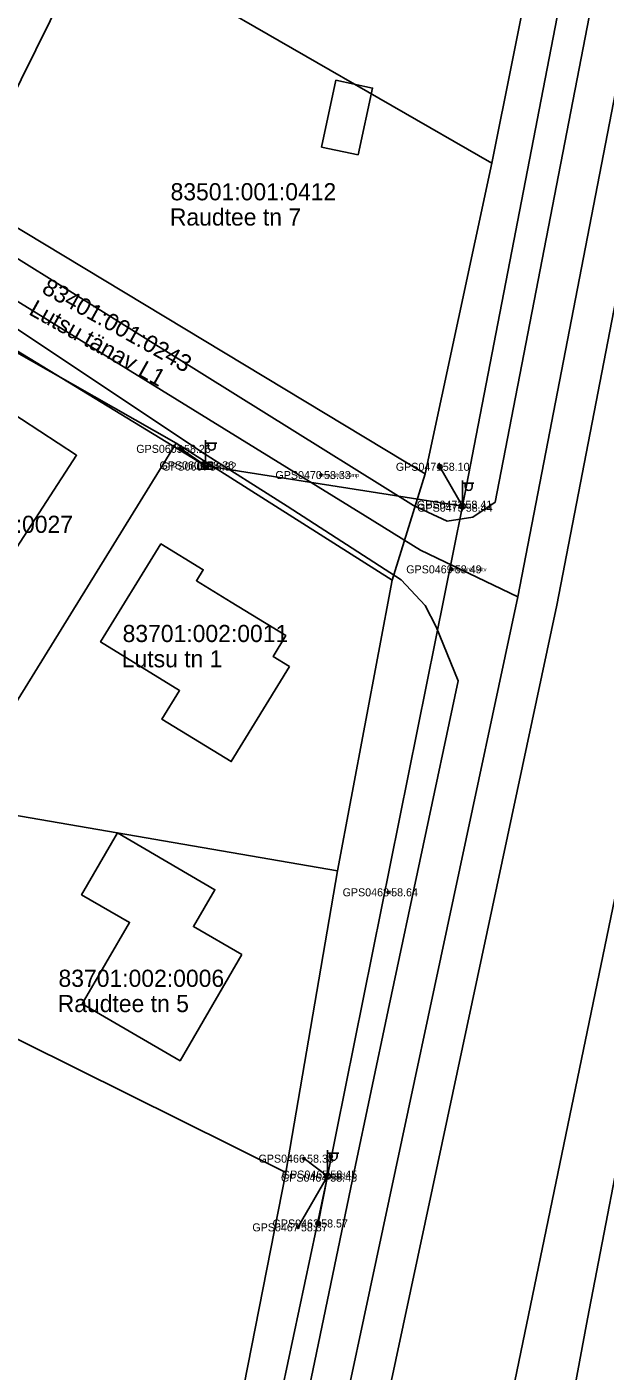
# Model space of a CAD drawing. Extents: x 580119 to 583377, y 6518915 to 6520820.
# Drawn here: x 582109.6 to 582160.2, y 6520100.4 to 6520218 of the extents above; entities that cross this region are included whole.
import ezdxf

# ---------------------------------------------------------------- set-up
doc = ezdxf.new("R2010")
doc.units = 0
for name, color, linetype in [('ELRAJATISMP', 7, 'Continuous'), ('Hoone Elu- või ühiskondlik hoone', 7, 'Continuous'), ('Hoone Vundament', 7, 'Continuous'), ('L_AADRESS', 7, 'Continuous'), ('MAAMUDEL', 7, 'Continuous'), ('MOOTKORG-EH2000', 7, 'Continuous'), ('MOOTMPUNKT', 7, 'Continuous'), ('MOOTNR', 7, 'Continuous'), ('MPOHULIIN', 7, 'Continuous'), ('PIIR', 7, 'Continuous'), ('POST', 7, 'Continuous'), ('SIOHULIIN', 7, 'Continuous'), ('Tee Liiklusala', 7, 'Continuous'), ('Tee Rada Pinnas', 7, 'Continuous'), ('Tee Tänav Püsikate', 7, 'Continuous'), ('TUNNUS', 7, 'Continuous')]:
    doc.layers.add(name, color=color, linetype=linetype)

msp = doc.modelspace()

# ---------------------------------------------------------------- linework, layer by layer
at = {"layer": 'ELRAJATISMP'}
for p, q in [((582125.12, 6520179.9), (582125.12, 6520179.3)), ((582125.4, 6520179.9), (582125.4, 6520179.3))]:
    msp.add_line(p, q, dxfattribs=at)
msp.add_lwpolyline([(582124.66, 6520179.9), (582125.86, 6520179.9), (582125.86, 6520179.3), (582124.66, 6520179.3)], close=True, dxfattribs=at)
at = {"layer": 'Hoone Elu- või ühiskondlik hoone'}
for points in [[(582104.3, 6520186.83), (582113.98, 6520180.53), (582108.38, 6520171.93), (582099.6, 6520177.65), (582097.77, 6520174.84), (582093.81, 6520177.43), (582098.18, 6520184.12), (582101.23, 6520182.13)], [(582132.61, 6520162.05), (582127.51, 6520153.73), (582121.45, 6520157.44), (582122.99, 6520159.95), (582116.07, 6520164.2), (582121.35, 6520172.78), (582125.06, 6520170.51), (582124.47, 6520169.55), (582127.5, 6520167.69), (582132.29, 6520164.75), (582131.17, 6520162.93)], [(582128.43, 6520136.86), (582123.03, 6520127.56), (582114.47, 6520132.53), (582118.61, 6520139.66), (582114.41, 6520142.09), (582117.55, 6520147.49), (582126.08, 6520142.53), (582124.2, 6520139.3)]]:
    msp.add_lwpolyline(points, close=True, dxfattribs=at)
at = {"layer": 'Hoone Vundament'}
msp.add_lwpolyline([(582138.62, 6520206.8), (582135.42, 6520207.48), (582136.68, 6520213.34), (582139.88, 6520212.65)], close=True, dxfattribs=at)
at = {"layer": 'MOOTMPUNKT'}
for centre in [(582123.12, 6520181.09), (582125.15, 6520179.65), (582125.37, 6520179.54), (582145.77, 6520179.52), (582135.37, 6520178.8), (582147.75, 6520176.21), (582147.78, 6520175.94), (582146.82, 6520170.55), (582141.25, 6520142.3), (582133.89, 6520119), (582135.92, 6520117.34), (582135.93, 6520117.61), (582133.35, 6520112.99), (582135.12, 6520113.33)]:
    msp.add_circle(centre, 0.1, dxfattribs=at)
at = {"layer": 'MPOHULIIN'}
msp.add_line((582135.93, 6520117.48), (582147.76, 6520176.08), dxfattribs=at)
for points in [[(582050.23, 6520344.28), (582083.18, 6520324.14), (582123.42, 6520299.31), (582167.33, 6520272.28), (582157.06, 6520224.19), (582147.76, 6520176.08), (582125.26, 6520179.6), (582101.28, 6520194.2)], [(582126.02, 6520070.82), (582135.93, 6520117.48)]]:
    msp.add_lwpolyline(points, dxfattribs=at)
at = {"layer": 'PIIR'}
for points in [[(582123.3, 6520072.1), (582132.28, 6520117.79), (582136.81, 6520144.18), (582141.59, 6520169.6), (582144.5, 6520178.9), (582150.31, 6520206.07), (582155.73, 6520232.98), (582164.12, 6520273.34), (582192.17, 6520260.67), (582184.32, 6520218.69), (582178.17, 6520186.47), (582175.35, 6520186.4), (582171.03, 6520165.68), (582166.86, 6520145.51), (582162.68, 6520125.68), (582158.7, 6520104.98), (582154.96, 6520084.94)], [(582058.52, 6520230.22), (582085.43, 6520214.53), (582104.08, 6520203.24), (582144.5, 6520178.9), (582141.59, 6520169.6), (582122.69, 6520181.59), (582100.91, 6520193.95), (582088.4, 6520176.42), (582091.24, 6520174.72), (582086.03, 6520166.05), (582081.69, 6520168.64), (582080.69, 6520170.63), (582096.96, 6520195.96), (582076.48, 6520208.35), (582056, 6520220.29), (582041.21, 6520194.04), (582035.33, 6520196.52), (582030.2, 6520198.89), (582046.99, 6520225.8)]]:
    msp.add_lwpolyline(points, dxfattribs=at)
for points in [[(582098.86, 6520242.4), (582108.08, 6520260.44), (582155.73, 6520232.98), (582150.31, 6520206.07), (582115.43, 6520226.17), (582116.98, 6520229.44), (582097.81, 6520240.35)], [(582085.43, 6520214.53), (582097.81, 6520240.35), (582116.98, 6520229.44), (582115.43, 6520226.17), (582104.08, 6520203.24)], [(582104.08, 6520203.24), (582115.43, 6520226.17), (582150.31, 6520206.07), (582144.5, 6520178.9)], [(582100.91, 6520193.95), (582122.69, 6520181.59), (582105.68, 6520154.1), (582086.03, 6520166.05), (582091.24, 6520174.72), (582088.4, 6520176.42)], [(582122.69, 6520181.59), (582141.59, 6520169.6), (582136.81, 6520144.18), (582104.8, 6520149.68), (582105.68, 6520154.1)], [(582104.8, 6520149.68), (582136.81, 6520144.18), (582132.28, 6520117.79), (582095.55, 6520136.02)], [(582087.7, 6520140.23), (582095.55, 6520136.02), (582132.28, 6520117.79), (582123.3, 6520072.1), (582069.55, 6520104.59)]]:
    msp.add_lwpolyline(points, close=True, dxfattribs=at)
at = {"layer": 'POST'}
for p, q in [((582125.26, 6520179.85), (582125.26, 6520181.85)), ((582125.26, 6520181.6), (582126.26, 6520181.6)), ((582125.49, 6520181.28), (582125.49, 6520181.6)), ((582126.1, 6520181.28), (582126.1, 6520181.6)), ((582125.26, 6520179.6), (582125.26, 6520179.6)), ((582147.76, 6520176.33), (582147.76, 6520178.33)), ((582147.76, 6520178.08), (582148.76, 6520178.08)), ((582147.99, 6520177.76), (582147.99, 6520178.08)), ((582148.6, 6520177.76), (582148.6, 6520178.08)), ((582147.76, 6520176.08), (582147.76, 6520176.08)), ((582135.93, 6520117.73), (582135.93, 6520119.73)), ((582135.93, 6520119.48), (582136.93, 6520119.48)), ((582136.15, 6520119.16), (582136.15, 6520119.48)), ((582136.77, 6520119.16), (582136.77, 6520119.48)), ((582135.93, 6520117.48), (582135.93, 6520117.48))]:
    msp.add_line(p, q, dxfattribs=at)
for points in [[(582123.12, 6520181.09), (582125.26, 6520179.6)], [(582145.77, 6520179.52), (582147.76, 6520176.08)], [(582135.93, 6520117.48), (582135.12, 6520113.33)]]:
    msp.add_lwpolyline(points, dxfattribs=at)
for centre, radius in [((582123.12, 6520181.09), 0.2), ((582125.26, 6520179.6), 0.25), ((582145.77, 6520179.52), 0.2), ((582147.76, 6520176.08), 0.25), ((582135.93, 6520117.48), 0.25), ((582135.12, 6520113.33), 0.2)]:
    msp.add_circle(centre, radius, dxfattribs=at)
for centre in [(582125.79, 6520181.28), (582148.3, 6520177.76), (582136.46, 6520119.16)]:
    msp.add_arc(centre, 0.306, 180, 0, dxfattribs=at)
at = {"layer": 'SIOHULIIN'}
msp.add_lwpolyline([(582133.89, 6520119), (582135.93, 6520117.48), (582133.35, 6520112.99)], dxfattribs=at)
at = {"layer": 'Tee Liiklusala'}
for points in [[(582213.27, 6520261.16), (582210.73, 6520261.47), (582201.46, 6520263.03), (582187.1, 6520266.01), (582184.99, 6520265.95), (582182.36, 6520265.63), (582179.84, 6520264.61), (582177.43, 6520262.81), (582175.72, 6520261.44), (582174.46, 6520259.31), (582173.61, 6520256.31), (582170.47, 6520241.47), (582167.69, 6520227.74), (582156.01, 6520167.41), (582145.12, 6520116.43), (582133.48, 6520061.96)], [(582058.8, 6520228.08), (582079.9, 6520215.68), (582104.12, 6520200.62), (582143.46, 6520176.14), (582146.42, 6520174.77), (582148.67, 6520175.11), (582150.61, 6520176.42), (582160.83, 6520229.13)], [(582130.29, 6520079.43), (582138.27, 6520117.89), (582141.26, 6520131.98), (582147.37, 6520160.79), (582145.45, 6520165.52), (582144.5, 6520167.39), (582142.4, 6520169.64), (582132.42, 6520176.08), (582124.85, 6520180.87), (582104.13, 6520194.65), (582102.42, 6520195.24), (582100.43, 6520195.05), (582098.76, 6520193.16), (582084.3, 6520168.83), (582082.71, 6520169.84), (582081.32, 6520171.06), (582097.74, 6520197.15), (582075.02, 6520211.28), (582071.14, 6520212.49), (582056.49, 6520221.77)]]:
    msp.add_lwpolyline(points, dxfattribs=at)
at = {"layer": 'Tee Rada Pinnas'}
msp.add_lwpolyline([(582120.7, 6519960.67), (582123.04, 6519966.42), (582130.88, 6520000), (582131.58, 6520002.99), (582133.37, 6520010.66), (582135.3, 6520018.94), (582144.54, 6520062.2), (582146.35, 6520070.66), (582174.6, 6520206.99), (582185.24, 6520261.1), (582187.1, 6520266.01), (582189.33, 6520270.5)], dxfattribs=at)
at = {"layer": 'Tee Tänav Püsikate'}
for points in [[(582179.69, 6520275), (582178.52, 6520273.19), (582172.44, 6520263.7), (582170.65, 6520258.76), (582164.26, 6520228.43), (582152.59, 6520168.14)], [(582100.43, 6520199.13), (582139.23, 6520175.24), (582144.09, 6520172.24), (582152.59, 6520168.14)], [(582152.59, 6520168.14), (582130.06, 6520062.7)]]:
    msp.add_lwpolyline(points, dxfattribs=at)

# ---------------------------------------------------------------- texts
at = {"layer": 'L_AADRESS'}
for s, p in [('Raudtee tn 7', (582122.14, 6520200.62)), ('Lutsu tn 1', (582117.93, 6520161.98)), ('Raudtee tn 5', (582112.32, 6520131.82))]:
    msp.add_text(s, height=1.5, dxfattribs=at).set_placement(p)
msp.add_text('Lutsu tänav L1', height=1.5, rotation=330.8609, dxfattribs=at).set_placement((582109.7, 6520192.89))
at = {"layer": 'MAAMUDEL'}
for s, p in [(' kaabel', (582125.37, 6520179.37)), (' mp_ohl7.05mp', (582135.37, 6520178.62)), (' mp_ohl6.50tv', (582146.82, 6520170.37)), (' tv', (582141.25, 6520142.13)), (' kaabel', (582135.92, 6520117.16)), (' kaabel', (582135.93, 6520117.44))]:
    msp.add_text(s, height=0.35, dxfattribs=at).set_placement(p)
at = {"layer": 'MOOTKORG-EH2000'}
for s, p in [(' 58.26', (582123.12, 6520180.74)), (' 58.26', (582125.15, 6520179.3)), (' 58.32', (582125.37, 6520179.19)), (' 58.10', (582145.77, 6520179.17)), (' 58.33', (582135.37, 6520178.45)), (' 58.41', (582147.75, 6520175.86)), (' 58.44', (582147.78, 6520175.59)), (' 58.49', (582146.82, 6520170.2)), (' 58.64', (582141.25, 6520141.95)), (' 58.38', (582133.89, 6520118.65)), (' 58.45', (582135.92, 6520116.99)), (' 58.45', (582135.93, 6520117.26)), (' 58.57', (582135.12, 6520112.98)), (' 58.37', (582133.35, 6520112.64))]:
    msp.add_text(s, height=0.7, dxfattribs=at).set_placement(p)
at = {"layer": 'MOOTNR'}
for s, p in [('GPS0605 ', (582119.2, 6520180.74)), ('GPS0606 ', (582121.23, 6520179.3)), ('GPS0607 ', (582121.45, 6520179.19)), ('GPS0471 ', (582141.92, 6520179.17)), ('GPS0470 ', (582131.38, 6520178.45)), ('GPS0472 ', (582143.76, 6520175.86)), ('GPS0473 ', (582143.79, 6520175.59)), ('GPS0469 ', (582142.83, 6520170.2)), ('GPS0468 ', (582137.26, 6520141.95)), ('GPS0466 ', (582129.9, 6520118.65)), ('GPS0464 ', (582131.86, 6520116.99)), ('GPS0465 ', (582131.94, 6520117.26)), ('GPS0463 ', (582131.13, 6520112.98)), ('GPS0467 ', (582129.36, 6520112.64))]:
    msp.add_text(s, height=0.7, dxfattribs=at).set_placement(p)
at = {"layer": 'TUNNUS'}
for s, p in [('83501:001:0412', (582122.2, 6520202.83)), ('83701:002:0027', (582099.16, 6520173.74)), ('83701:002:0011', (582118, 6520164.19)), ('83701:002:0006', (582112.39, 6520134.03))]:
    msp.add_text(s, height=1.5, dxfattribs=at).set_placement(p)
msp.add_text('83401:001:0243', height=1.5, rotation=330.8609, dxfattribs=at).set_placement((582110.83, 6520194.78))

doc.saveas('drawing.dxf')
